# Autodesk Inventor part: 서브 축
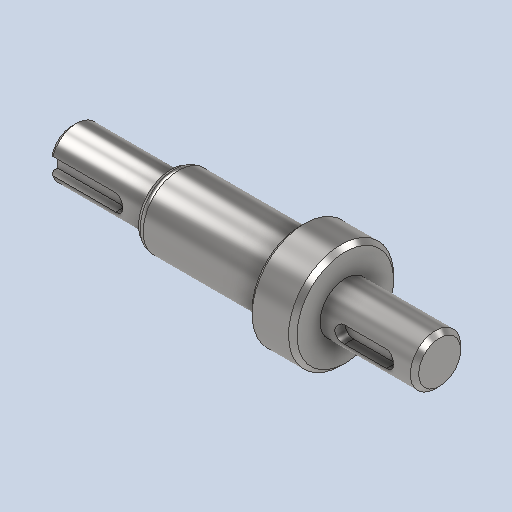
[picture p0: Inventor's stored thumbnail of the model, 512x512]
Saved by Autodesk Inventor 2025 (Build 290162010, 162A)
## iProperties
Created: 2024-07
Part Number: 서브 축
Material: 강철, 연강
Document SubType Name: Modeling
Designer: 계정
Density: 7.86 g/cm^3
Appearance: 기본값
Author: jhkim
Revision Number: 1
Sending System: Autodesk Inventor 2025
Preprocessor: ST-DEVELOPER v20
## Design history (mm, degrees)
feature "솔리드1"
node "솔리드2"
